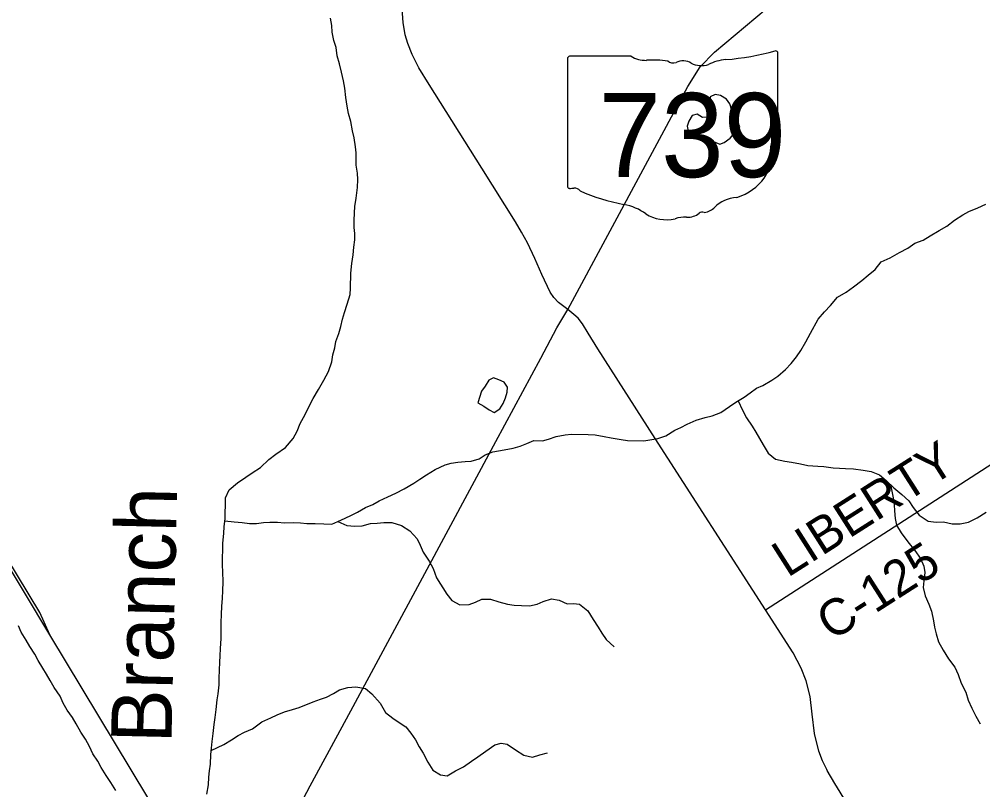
# Model space of a CAD drawing. Extents: x 0 to 34, y 0 to 22.
# Drawn here: x 3.154 to 3.909, y 14.479 to 15.083 of the extents above; entities that cross this region are included whole.
import ezdxf

# ---------------------------------------------------------------- set-up
doc = ezdxf.new("R2010")
doc.units = 0
for name, color, linetype in [('GM_X_County_Road', 7, 'Continuous'), ('GM_X_County_Road_Text', 7, 'Continuous'), ('GM_X_Minor_Lake', 7, 'Continuous'), ('GM_X_Minor_River', 7, 'Continuous'), ('GM_X_Minor_River_Text', 7, 'Continuous'), ('GM_X_Rail_Line', 7, 'Continuous'), ('GM_X_State_Location', 7, 'Continuous'), ('GM_X_State_Route', 7, 'Continuous'), ('GM_X_State_Shield', 7, 'Continuous')]:
    doc.layers.add(name, color=color, linetype=linetype)

msp = doc.modelspace()

# ---------------------------------------------------------------- linework, layer by layer
at = {"layer": 'GM_X_County_Road'}
for points in [[(3.73858, 14.6201), (3.92413, 14.73981), (4.02401, 14.80426), (4.34376, 15.01102), (4.352, 15.01643), (4.35746, 15.02065), (4.35939, 15.0236), (4.36105, 15.02788), (4.36153, 15.03334), (4.361, 15.03869), (4.35907, 15.04329), (4.35215, 15.05378), (4.30603, 15.12588), (4.62047, 15.25782), (4.86354, 15.27723), (5.11731, 15.29779), (5.27906, 15.31173)], [(3.59973, 14.83697), (3.59524, 14.84415), (3.59177, 14.8487), (3.58857, 14.8516), (3.58386, 14.85541), (3.57651, 14.86104), (3.57291, 14.86488), (3.57, 14.86902), (3.56355, 14.88291), (3.55803, 14.89547), (3.55224, 14.90782), (3.54759, 14.91611), (3.54272, 14.92429), (3.51631, 14.96635), (3.47508, 15.03182), (3.467, 15.04502), (3.46178, 15.05527), (3.45836, 15.06404), (3.45646, 15.07083), (3.45474, 15.0805), (3.454, 15.09103)], [(3.78658, 14.49513), (3.78336, 14.50174), (3.78037, 14.50945), (3.77716, 14.52325), (3.77519, 14.53845), (3.77352, 14.55226), (3.77052, 14.56457), (3.76666, 14.57442), (3.76035, 14.58641), (3.73858, 14.6201), (3.65229, 14.75434), (3.60741, 14.82474), (3.59973, 14.83697)], [(4.0153, 14.12288), (4.00982, 14.1309), (3.79299, 14.48392), (3.787, 14.49424), (3.78658, 14.49513)]]:
    msp.add_lwpolyline(points, dxfattribs=at)
at = {"layer": 'GM_X_Minor_Lake'}
for points in [[(3.70295, 14.98517), (3.70637, 14.98648), (3.71093, 14.98986), (3.71532, 14.99496), (3.71856, 14.99874), (3.71668, 15.00273), (3.71481, 15.00691), (3.71199, 15.01243), (3.71069, 15.0166), (3.70805, 15.02041), (3.70352, 15.02309), (3.69935, 15.02406), (3.69537, 15.02218), (3.69477, 15.01725), (3.69703, 15.01307), (3.6972, 15.00909), (3.69516, 15.00758)], [(3.69516, 15.00758), (3.69339, 15.00626), (3.68922, 15.0061), (3.68507, 15.00858), (3.68108, 15.00766), (3.6786, 15.00312), (3.67725, 14.99914), (3.67799, 14.99516), (3.68234, 14.99267), (3.68707, 14.99132), (3.69104, 14.98997), (3.69482, 14.98843), (3.70295, 14.98517)], [(3.53488, 14.79709), (3.53393, 14.79853), (3.52977, 14.80045), (3.52561, 14.80199), (3.52181, 14.80011), (3.51895, 14.79539), (3.51627, 14.79161), (3.51319, 14.78234)], [(3.51319, 14.78234), (3.51792, 14.77966), (3.52207, 14.77679), (3.52604, 14.77487), (3.53041, 14.7777), (3.53309, 14.78185), (3.535, 14.7862), (3.53636, 14.79075), (3.53656, 14.79454), (3.53488, 14.79709)]]:
    msp.add_lwpolyline(points, dxfattribs=at)
at = {"layer": 'GM_X_Minor_River'}
for points in [[(3.41698, 14.93622), (3.41796, 14.94285), (3.41894, 14.951), (3.41917, 14.95744), (3.419, 14.96237), (3.41809, 14.96863), (3.41792, 14.97356), (3.41795, 14.9783), (3.41759, 14.98305), (3.4163, 14.99007), (3.415, 14.99557), (3.4139, 15.00278), (3.41185, 15.00924), (3.41093, 15.01494), (3.41001, 15.02177), (3.4091, 15.02898), (3.40818, 15.03467), (3.40651, 15.0415), (3.40484, 15.04815), (3.40316, 15.05442), (3.40225, 15.06087), (3.40057, 15.06619), (3.39928, 15.07283), (3.39892, 15.07814), (3.398, 15.08384)], [(3.31513, 14.69), (3.32246, 14.68912), (3.32871, 14.68851), (3.33439, 14.68773), (3.33989, 14.6877), (3.34539, 14.68862), (3.35031, 14.68878), (3.35638, 14.68875), (3.36187, 14.68834), (3.36888, 14.6885), (3.37438, 14.68828), (3.3793, 14.68787), (3.38593, 14.68784), (3.39256, 14.68761), (3.39881, 14.68739), (3.40356, 14.68926), (3.40926, 14.69208), (3.4142, 14.69432), (3.41895, 14.69676), (3.42522, 14.70033), (3.43111, 14.70277), (3.43605, 14.70558), (3.44289, 14.70877), (3.44916, 14.71158), (3.45562, 14.71496), (3.46322, 14.71947), (3.46797, 14.72248), (3.47311, 14.72586), (3.47995, 14.73019), (3.48774, 14.73375), (3.49248, 14.73505), (3.4976, 14.73597), (3.50329, 14.73632), (3.50803, 14.73668), (3.51429, 14.73854), (3.51904, 14.74155), (3.52512, 14.74398), (3.53384, 14.74545), (3.54086, 14.74693), (3.54636, 14.74842), (3.55168, 14.75048), (3.55719, 14.75272), (3.56401, 14.75269), (3.56875, 14.75399), (3.57464, 14.75585), (3.58184, 14.75733), (3.58677, 14.75769), (3.59966, 14.75762), (3.60534, 14.75721), (3.61234, 14.75604), (3.61783, 14.75487), (3.62559, 14.7535), (3.63051, 14.75272), (3.6434, 14.75265), (3.64966, 14.75357), (3.6544, 14.75449), (3.66066, 14.75654), (3.66751, 14.76106), (3.67244, 14.76312), (3.6772, 14.76575), (3.68422, 14.76874), (3.69143, 14.77098), (3.69693, 14.77209), (3.70377, 14.77471), (3.71043, 14.77941), (3.71537, 14.7828), (3.72183, 14.78675), (3.72659, 14.79032), (3.73172, 14.7939), (3.73666, 14.79596), (3.7435, 14.80009), (3.74825, 14.80329), (3.75434, 14.80838), (3.75873, 14.81329), (3.76292, 14.81838), (3.76636, 14.82329), (3.77037, 14.8301), (3.77401, 14.83709), (3.77994, 14.84806), (3.7849, 14.85372), (3.78947, 14.85863), (3.795, 14.86523), (3.80184, 14.86918), (3.80754, 14.87332), (3.81401, 14.87822), (3.81896, 14.88236), (3.82467, 14.88688), (3.82924, 14.89293), (3.83627, 14.89593), (3.84368, 14.90025), (3.85014, 14.90363), (3.85565, 14.90739), (3.8623, 14.90982), (3.86762, 14.91321), (3.87465, 14.91753), (3.88073, 14.92091), (3.88682, 14.92562), (3.89328, 14.92976), (3.89803, 14.9322), (3.90487, 14.9352), (3.91132, 14.93801)], [(3.30103, 14.4758), (3.3022, 14.483), (3.30262, 14.48906), (3.30321, 14.49398), (3.30381, 14.4991), (3.30423, 14.50668), (3.30464, 14.5116), (3.30523, 14.51691), (3.30584, 14.52335), (3.30682, 14.53036), (3.30761, 14.53585), (3.3084, 14.54191), (3.3092, 14.54949), (3.3098, 14.55441), (3.31059, 14.56142), (3.31062, 14.56654), (3.31104, 14.57298), (3.31126, 14.57905), (3.31147, 14.58416), (3.3117, 14.58985), (3.31212, 14.59762), (3.31218, 14.60994), (3.31241, 14.61676), (3.31263, 14.62282), (3.31324, 14.62926), (3.31346, 14.63514), (3.31368, 14.64196), (3.31354, 14.64993), (3.31338, 14.65523), (3.31322, 14.66073), (3.31344, 14.66736), (3.31366, 14.67248), (3.31427, 14.68006), (3.31467, 14.68537), (3.31527, 14.69143), (3.3153, 14.69655), (3.31571, 14.70166), (3.31574, 14.70792), (3.31862, 14.71416), (3.32509, 14.71962), (3.33156, 14.72414), (3.3365, 14.72752), (3.34296, 14.73166), (3.34963, 14.73807), (3.35515, 14.74221), (3.36256, 14.74729), (3.36866, 14.75446), (3.37173, 14.76014), (3.37403, 14.76619), (3.37805, 14.77318), (3.38035, 14.7781), (3.38418, 14.78566), (3.38857, 14.79284), (3.39278, 14.80003), (3.39641, 14.80702), (3.39892, 14.8144), (3.3997, 14.82009), (3.40125, 14.82539), (3.40203, 14.8305), (3.40453, 14.83674), (3.40588, 14.84223), (3.40724, 14.84791), (3.40897, 14.85303), (3.4109, 14.85965), (3.41321, 14.86722), (3.41362, 14.87215), (3.41368, 14.88409), (3.41447, 14.89167), (3.41565, 14.8983), (3.41624, 14.90437), (3.41684, 14.91005), (3.41687, 14.91498), (3.41651, 14.91972), (3.41635, 14.92522), (3.41657, 14.93129), (3.41698, 14.93622)], [(3.71736, 14.78401), (3.72064, 14.77651), (3.72383, 14.77062), (3.72816, 14.76415), (3.73097, 14.7594), (3.73398, 14.75445), (3.73679, 14.74932), (3.74074, 14.74285), (3.7464, 14.73809), (3.75378, 14.73653), (3.75908, 14.73593), (3.76608, 14.73457), (3.77176, 14.73321), (3.77953, 14.7328), (3.78445, 14.73239), (3.79165, 14.73141), (3.79657, 14.73119), (3.80131, 14.73098), (3.80756, 14.73075), (3.81513, 14.72958), (3.82138, 14.7286), (3.828, 14.72591), (3.83328, 14.72152), (3.83931, 14.7158), (3.84535, 14.71065), (3.851, 14.7055), (3.85438, 14.70037), (3.85909, 14.69428), (3.86607, 14.6895), (3.87232, 14.6889), (3.87801, 14.68906), (3.88482, 14.68751), (3.89107, 14.68748), (3.89771, 14.68877), (3.90436, 14.69234), (3.9114, 14.69666)], [(3.83669, 14.71829), (3.8387, 14.70784), (3.83943, 14.70234), (3.83959, 14.6976), (3.84013, 14.69172), (3.84124, 14.6866), (3.84481, 14.68051), (3.85007, 14.67347), (3.85572, 14.66662), (3.86004, 14.66034), (3.86266, 14.65445), (3.8634, 14.64933), (3.86279, 14.64289), (3.8622, 14.63777), (3.86368, 14.63113), (3.86667, 14.62448), (3.86873, 14.61897), (3.87039, 14.61157), (3.87112, 14.60664), (3.87223, 14.60133), (3.87428, 14.59506), (3.87784, 14.58841), (3.88198, 14.58175), (3.88706, 14.57509), (3.88949, 14.56939), (3.89191, 14.56256), (3.89547, 14.55552), (3.89752, 14.54926), (3.90033, 14.54299), (3.90333, 14.53691), (3.9069, 14.53082)], [(3.40356, 14.68926), (3.41075, 14.68619), (3.41699, 14.68559), (3.42268, 14.68594), (3.42932, 14.6878), (3.43444, 14.68815), (3.43975, 14.6885), (3.446, 14.68847), (3.45357, 14.68616), (3.45999, 14.68195), (3.46583, 14.67567), (3.46808, 14.67092), (3.47051, 14.66522), (3.47521, 14.65818), (3.47821, 14.65248), (3.48101, 14.64526), (3.4889, 14.63233), (3.49304, 14.62757), (3.49928, 14.62412), (3.50648, 14.62428), (3.5116, 14.62614), (3.51654, 14.62839), (3.52318, 14.62855), (3.52979, 14.62643), (3.53642, 14.6245), (3.54172, 14.6239), (3.5474, 14.62349), (3.55365, 14.62327), (3.55972, 14.62457), (3.56447, 14.62663), (3.57092, 14.62868), (3.57698, 14.6277), (3.58341, 14.62482), (3.58815, 14.62518), (3.59307, 14.62458), (3.59949, 14.61943), (3.60362, 14.61259), (3.60756, 14.6065), (3.61057, 14.60174), (3.61395, 14.5968), (3.62017, 14.59108)], [(3.2298, 14.47845), (3.22566, 14.48472), (3.2221, 14.49043), (3.21834, 14.4967), (3.21572, 14.50145), (3.21177, 14.50716), (3.20896, 14.51305), (3.20596, 14.51875), (3.2022, 14.52427), (3.19863, 14.53073), (3.19582, 14.53586), (3.19168, 14.54157), (3.18849, 14.5469), (3.18606, 14.5524), (3.18136, 14.55925), (3.17835, 14.56476), (3.17535, 14.56971), (3.17253, 14.57446), (3.16878, 14.58055), (3.16615, 14.5853), (3.16239, 14.59138), (3.15958, 14.59633), (3.15563, 14.6026), (3.15358, 14.60773)], [(3.3045, 14.50998), (3.31432, 14.51459), (3.3204, 14.51834), (3.32553, 14.52173), (3.33048, 14.52436), (3.33674, 14.52698), (3.34397, 14.53225), (3.35119, 14.53562), (3.35613, 14.53787), (3.36183, 14.5403), (3.36809, 14.54198), (3.37321, 14.54347), (3.38423, 14.54796), (3.39011, 14.55001), (3.39486, 14.55169), (3.40018, 14.55451), (3.40493, 14.55733), (3.41138, 14.55938), (3.41783, 14.55972), (3.42521, 14.55836), (3.43031, 14.55435), (3.4369, 14.54693), (3.44084, 14.5397), (3.44669, 14.53531), (3.45159, 14.53187), (3.45688, 14.52844), (3.46083, 14.52349), (3.4644, 14.51816), (3.46722, 14.51284), (3.47041, 14.50771), (3.47416, 14.50086), (3.4781, 14.4944), (3.48415, 14.49095), (3.48926, 14.48998), (3.49591, 14.49393), (3.50199, 14.49712), (3.50827, 14.50163), (3.51321, 14.50483), (3.51968, 14.50934), (3.52653, 14.51443), (3.53146, 14.51554), (3.53639, 14.51475), (3.5428, 14.51036), (3.54922, 14.50635), (3.55604, 14.50479), (3.56192, 14.50647), (3.56799, 14.50814)]]:
    msp.add_lwpolyline(points, dxfattribs=at)
at = {"layer": 'GM_X_Rail_Line'}
for points in [[(3.17806, 14.60062), (3.1182, 14.70018), (2.92606, 15.01768), (2.82675, 15.18408), (2.8108, 15.21209)], [(3.17806, 14.60062), (3.17015, 14.61816), (3.05589, 14.80722), (2.92293, 15.02814), (2.91491, 15.04458), (2.9071, 15.06451), (2.90625, 15.06632)], [(3.31164, 14.37795), (3.30957, 14.38168), (3.30533, 14.38893), (3.17806, 14.60062)]]:
    msp.add_lwpolyline(points, dxfattribs=at)
at = {"layer": 'GM_X_State_Route'}
for p, q in [((3.46987, 14.64523), (3.52744, 14.75199)), ((3.41372, 14.54109), (3.46987, 14.64523))]:
    msp.add_line(p, q, dxfattribs=at)
for points in [[(3.52744, 14.75199), (3.56275, 14.81746), (3.57522, 14.84103), (3.58386, 14.85541), (3.67772, 15.0303), (3.6875, 15.04562), (3.69872, 15.05726), (3.73927, 15.09103), (3.79473, 15.13521), (4.05149, 15.34396), (4.48401, 15.69487), (4.64997, 15.82965)], [(3.34805, 14.42112), (3.35415, 14.43057), (3.3695, 14.45843), (3.38197, 14.48222), (3.41372, 14.54109)]]:
    msp.add_lwpolyline(points, dxfattribs=at)
at = {"layer": 'GM_X_State_Shield'}
for p, q in [((3.5836, 15.05225), (3.5836, 14.95219)), ((3.63348, 15.05398), (3.58522, 15.05398)), ((3.74839, 15.00411), (3.74839, 15.05646)), ((3.74838, 15.00413), (3.74839, 15.00411))]:
    msp.add_line(p, q, dxfattribs=at)
for centre, major_axis, start_param, end_param in [((3.68969, 15.19039), (0.17476, 0), 4.814394, 5.042369), ((3.74656, 15.05667), (0.00183, 0), 6.141152, 7.989035), ((3.58549, 15.05247), (0.00191, 0), 1.712693, 3.28349), ((3.64498, 15.06559), (0.01852, 0), 4.042523, 4.731795), ((3.65112, 14.9978), (0.06648, 0), 1.404758, 1.657858), ((3.67405, 15.04142), (0.01111, 0), 0.950623, 2.079405), ((3.71198, 15.02342), (0.03516, 0), 1.699011, 2.107814), ((3.66621, 15.05299), (0.00534, 0), 3.836095, 5.185415), ((3.68839, 15.05728), (0.01336, 0), 4.081561, 5.145723), ((3.74797, 15.00027), (0.00284, 0), 1.883978, 3.671073), ((3.72991, 14.99365), (0.01704, 0), 5.934695, 6.695948), ((3.74644, 15.00391), (0.00196, 0), 5.05454, 6.418171), ((3.75497, 14.98221), (0.0124, 0), 2.387724, 3.262537), ((3.69948, 14.97555), (0.04371, 0), 5.101752, 6.440018), ((3.58551, 14.95198), (0.00193, 0), 3.00124, 4.508301), ((3.5858, 14.96221), (0.0147, 0), 4.665946, 4.897461), ((3.58881, 14.94642), (0.0053, 0), 0.519207, 1.627899), ((3.65572, 15.03632), (0.1262, 0), 4.195997, 4.488961), ((3.61809, 14.90724), (0.03949, 0), 0.823519, 1.323587), ((3.71791, 14.9241), (0.02394, 0), 1.647645, 2.488434), ((3.6608, 14.94593), (0.02506, 0), 4.026481, 4.996735), ((3.67711, 14.93843), (0.01335, 0), 4.691044, 5.507374), ((3.68918, 14.92874), (0.00376, 0), 1.147584, 2.315152), ((3.68758, 14.9425), (0.01412, 0), 4.937069, 5.64225), ((3.67528, 14.91133), (0.02059, 0), 1.495662, 1.94098)]:
    msp.add_ellipse(centre, major_axis=major_axis, ratio=0.8, start_param=start_param, end_param=end_param, dxfattribs=at)

# ---------------------------------------------------------------- texts
at = {"layer": 'GM_X_County_Road_Text'}
for s, rotation, p in [('LIBERTY', 32.47152, (3.75597, 14.64505)), ('C-125', 32.61924, (3.79066, 14.5953))]:
    msp.add_text(s, height=0.028409, rotation=rotation, dxfattribs=at).set_placement(p)
at = {"layer": 'GM_X_Minor_River_Text'}
msp.add_text('Branch', height=0.047353, rotation=88.70847, dxfattribs=at).set_placement((3.27324, 14.51524))
at = {"layer": 'GM_X_State_Location'}
for s, p in [('s', (3.66415, 14.99557)), ('r', (3.66414, 14.99557))]:
    msp.add_text(s, height=0.0000947, dxfattribs=at).set_placement(p)
msp.add_text('739', height=0.0000947, rotation=0.00001, dxfattribs=at).set_placement((3.63072, 14.98868))
at = {"layer": 'GM_X_State_Shield'}
msp.add_text('739', height=0.065918, dxfattribs=at).set_placement((3.60784, 14.95925))

doc.saveas('drawing.dxf')
